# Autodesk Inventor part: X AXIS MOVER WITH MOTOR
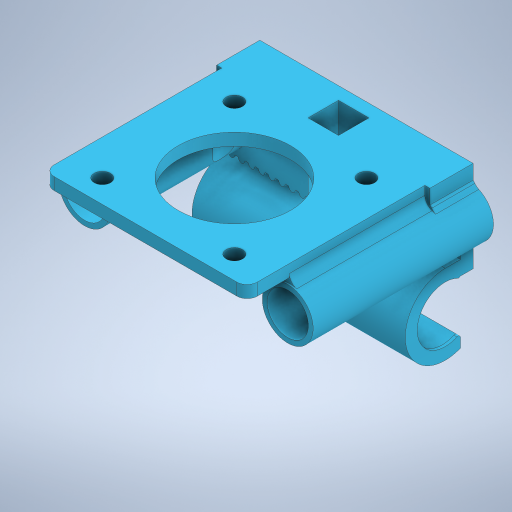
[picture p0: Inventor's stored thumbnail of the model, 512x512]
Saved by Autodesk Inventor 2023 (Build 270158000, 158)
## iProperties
Created: 2025-07
Part Number: X AXIS MOVER WITH MOTOR
Material: Generic
Document SubType Name: Modeling
Designer: erjon
Density: 1 g/cm^3
Appearance: Default
Author: erjon
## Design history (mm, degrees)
feature "Base1"
sketch "Sketch1"
  geometry: L1 (-7, 2)-(-7, -0.943); L2 (-9.308, -3.538)-(-9.241, -3.404) reference; L3 (-5, -5)-(-9, -5) reference; L4 (0, 10.101)-(0, 0) reference; L5 (-9.399, 7.335)-(-9.5, 7.5) reference; L6 (-10, 8)-(-10, 9) reference; L7 (-10, 9)-(0, 9); L8 (-4.692, -3.538)-(-4.759, -3.404); L9 (-9, -5)-(-5, -5); L10 (-14, 10.101)-(-14, 0); L11 (-4.601, 7.335)-(-4.5, 7.5); L12 (-4, 8)-(-4, 9); L13 (-4, 9)-(-14, 9); A1 r 5.85 centre (-7, 2) between (-9.241, -3.404) and (-9.399, 7.335) reference; A2 r 1 centre (-9, -4) between (-10, -4) and (-9, -5) reference; A3 r 0.5 centre (-9.5, -4) between (-9.308, -3.538) and (-10, -4) reference; A4 r 5 centre (-5, 0) between (-5, -5) and (0, 0) reference; A5 r 0.5 centre (-9.5, 8) between (-10, 8) and (-9.5, 7.5) reference; A6 r 0.5 centre (-4.5, -4) between (-4, -4) and (-4.692, -3.538); A7 r 1 centre (-5, -4) between (-5, -5) and (-4, -4); A8 r 5 centre (-9, 0) between (-14, 0) and (-9, -5); A9 r 5.85 centre (-7, 2) between (-4.601, 7.335) and (-4.759, -3.404); A10 r 0.5 centre (-4.5, 8) between (-4.5, 7.5) and (-4, 8); 9 further points
  constraints: 16 end point, 16 symmetric about line, 10 point on circle, 5 centre point, 2 point on line, 1 perpendicular, 1 vertical, 5 other
extrude "Extrusion1" join sketch "Sketch1" stored distance "d0" = 10; taper "d1" = 0 deg
sketch "Sketch2"
  geometry: L1 (-4.601, 7.335)-(0, 7.335); L2 (0, 0)-(0, 10.101) reference; A1 r 5.85 centre (-7, 2) between (-9.241, -3.404) and (-9.399, 7.335) reference; 1 further point
  constraints: 2 end point, 1 horizontal, 1 point on circle, 1 point on line
extrude "Extrusion2" cut sketch "Sketch1" distance "d2" = 100; taper "d3" = 0 deg
sketch "Sketch3"
  geometry: L1 (9.399, 7.335)-(9.5, 7.5) reference; L2 (10, 8)-(10, 9) reference; L3 (4, 9)-(14, 9) reference; L4 (14, 0)-(14, 10.101) reference; L5 (9.399, 7.335)-(14, 7.335) reference; A1 r 0.5 centre (9.5, 8) between (9.5, 7.5) and (10, 8) reference; 1 further point
extrude "Extrusion3" join sketch "Sketch3" stored distance "d4" = 100; taper "d5" = 0 deg
sketch "Sketch4"
  geometry: L1 (42, -15.065)-(42, -12.299) reference; L2 (42, 0)-(42, -1.858) reference; L3 (0, 0)-(42, 0) reference; L4 (0, 0)-(0, -1.858) reference; L5 (0, -12.299)-(0, -15.065) reference; L6 (0, -15.065)-(42, -15.065) reference; A1 r 5 centre (41, -7.4) between (42, -12.299) and (43.122, -2.873) reference; A2 r 2 centre (43.971, -1.062) between (42.348, -2.231) and (43.122, -2.873) reference; A3 r 2 centre (40.726, -3.4) between (42.348, -2.231) and (42, -1.858) reference; A4 r 2 centre (1.274, -3.4) between (0, -1.858) and (-0.348, -2.231) reference; A5 r 2 centre (-1.971, -1.062) between (-1.122, -2.873) and (-0.348, -2.231) reference; A6 r 5 centre (1, -7.4) between (-1.122, -2.873) and (0, -12.299) reference; 1 further point
extrude "Extrusion4" cut sketch "Sketch4" distance "d6" = 1.5; taper "d7" = 0 deg
sketch "Sketch5"
  geometry: L1 (29.255, -6)-(-0.745, -6); L2 (14.255, -6)-(14.255, -11.978); L3 (14.255, -11.978)-(11.256, -12); L4 (35.255, -12)-(-6.745, -12) reference; L5 (11.256, -12)-(17.256, -12); L6 (17.256, -12)-(17.256, 0); L7 (25.305, 0)-(3.205, 0) reference; L8 (17.256, 0)-(11.256, 0); L9 (11.256, 0)-(11.256, -13.665); L10 (-6.745, -13.665)-(35.255, -13.665) reference; A1 r 5 centre (34.255, -6) between (30.465, -2.739) and (35.255, -10.899) reference; A2 r 5 centre (-5.745, -6) between (-6.745, -10.899) and (-1.641, -3.143) reference; 3 further points
  constraints: 14 end point, 4 point on line, 3 perpendicular, 2 point on circle, 1 horizontal, 1 midpoint, 1 vertical
  dimensions: "d8" = 3 distance of L2.end L3.end; "d9" = 6 distance of L3.end L5.end; "d10" = 6 distance of L6.end L8.end
extrude "Extrusion5" cut sketch "Sketch5" distance "d11" = 6; taper "d12" = 0 deg
sketch "Sketch6"
  geometry: L1 (34.087, -35)-(34.087, -8.324) reference; L2 (34.087, -8.324)-(38, -8.324) reference; L3 (38, -2)-(38, -8.324) reference; L4 (0, 0)-(36, 0) reference; L5 (-2, -8)-(-2, -2) reference; L6 (-2, -8)-(3.745, -8) reference; L7 (3.745, -29.508)-(3.745, -8) reference; L8 (3.745, -35)-(3.745, -31.492) reference; L9 (15, -35)-(3.745, -35) reference; L10 (15, -35)-(15, -41) reference; L11 (15, -41)-(21, -41) reference; L12 (21, -35)-(21, -41) reference; L13 (34.087, -35)-(21, -35) reference; L14 (21, -35)-(15, -35); C1 r 1.6 at (31, -4.5) reference; C2 r 1.6 at (5, -4.5) reference; C3 r 1.6 at (31, -30.5) reference; C4 r 11.05 at (18, -17.5) reference; A1 r 2 centre (36, -2) between (38, -2) and (36, 0) reference; A2 r 2 centre (0, -2) between (0, 0) and (-2, -2) reference; A3 r 1.6 centre (5, -30.5) between (3.745, -31.492) and (3.745, -29.508) reference; 1 further point
  constraints: 2 end point, 1 horizontal
extrude "Extrusion6" cut sketch "Sketch6" distance "d13" = 6; taper "d14" = 0 deg
sketch "Sketch7"
  geometry: L1 (-6, 0)-(0, 0) reference; L2 (-6, 0)-(-6, -0.8); L3 (-6, -0.148)-(-6, 0) reference; L4 (-6, -0.8)-(4, -0.8); L5 (4, -0.148)-(4, -9.148) reference; L6 (4, -0.8)-(4, 0); L7 (4, 0)-(-6, 0); 3 further points
  constraints: 8 end point, 2 perpendicular, 1 collinear, 1 point on line, 1 vertical
  dimensions: "d15" = 0.8 distance of L1.start L2.end
extrude "Extrusion7" cut sketch "Sketch7" distance "d16" = 100; taper "d17" = 0 deg
fillet "Fillet1" dims "d18" = 4
sketch "Sketch8"
  geometry: L1 (0, -0.8)-(-6, -0.8) reference; L2 (-6, -0.8)-(-6, 0) reference; L3 (-6, 0)-(0, 0) reference; L4 (0, 0)-(0, 0.953) reference; L5 (0, 0.953)-(-8.5, 0.953) reference; L6 (-8.5, 0.953)-(-8.5, -1.813) reference; L7 (-5.399, -1.813)-(-8.5, -1.813) reference; L8 (-5.241, -12.552)-(-5.308, -12.686) reference; L9 (-5, -14.148)-(-1, -14.148) reference; L10 (4, -4.8)-(4, -9.148) reference; L11 (-6, -0.8)-(-8.5, -0.8); A1 r 4 centre (0, -4.8) between (4, -4.8) and (0, -0.8) reference; A2 r 5.85 centre (-3, -7.148) between (-5.241, -12.552) and (-5.399, -1.813) reference; A3 r 0.5 centre (-5.5, -13.148) between (-5.308, -12.686) and (-6, -13.148) reference; A4 r 1 centre (-5, -13.148) between (-6, -13.148) and (-5, -14.148) reference; A5 r 5 centre (-1, -9.148) between (-1, -14.148) and (4, -9.148) reference; 1 further point
  constraints: 2 end point, 1 perpendicular, 1 point on line
extrude "Extrusion8" cut sketch "Sketch8" distance "d19" = 100; taper "d20" = 0 deg
sketch "Sketch9"
  geometry: L1 (0, 0.005)-(-6, 0.005) reference; L2 (-6, 0.005)-(-6, -0.895); L3 (-6, -0.895)-(-8.5, -0.895); L4 (-6, -0.8)-(-8.5, -0.8) reference; L5 (-8.5, -0.895)-(-8.5, -0.8); L6 (-8.5, -0.895)-(-8.5, -2.895); L7 (-8.5, -2.895)-(0, -2.895); L8 (0, -2.895)-(0, -0.895); L9 (-6, -0.895)-(0, -0.895); L10 (-8.5, -2.895)-(-8.5, -8.745); L11 (-8.5, -8.745)-(-3, -8.745); L12 (-6, -0.895)-(-6, -16); L13 (-8.5, -0.8)-(-6, -0.8) reference; L14 (-6, -0.8)-(-6, 0) reference; L15 (-6, 0)-(0, 0) reference; L16 (0, 0)-(0, 0.953) reference; L17 (0, 0.953)-(-8.5, 0.953) reference; L18 (-8.5, 0.953)-(-8.5, -0.8) reference; L19 (-6, -3.723)-(-8.5, -3.723); 5 further points
  constraints: 22 end point, 8 perpendicular, 3 vertical, 2 coincident, 2 point on line, 1 horizontal, 6 other
  dimensions: "d21" = 0.9 distance of L1.end L2.end; "d22" = 2 distance of L3.end L6.end; "d23" = 5.85 distance of L6.end L10.end; "d24" = 5.5 distance of L10.end L11.end
extrude "Extrusion9" join sketch "Sketch9" stored distance "d25" = 100; taper "d26" = 0 deg
sketch "Sketch10"
  geometry: L1 (-6, -0.895)-(-6, 0) reference; L2 (-6, 0)-(0, 0) reference; L3 (0, 0)-(0, 0.953) reference; L4 (0, 0.953)-(-8.5, 0.953) reference; L5 (-8.5, 0.953)-(-8.5, -3.723) reference; L6 (-8.5, -3.723)-(-6, -3.723) reference; L7 (-6, -13.768)-(-6, -16) reference; L8 (-3, -0.895)-(-6, -0.895) reference; L9 (-6, -13.768)-(-6, -3.723); C1 r 5.85 at (-3, -8.745); C2 r 5.5 at (-3, -8.745); A1 r 5.85 centre (-3, -8.745) between (-6, -13.768) and (-6, -3.723) reference; A2 r 7.85 centre (-3, -8.745) between (-6, -16) and (-3, -0.895) reference; 3 further points
  constraints: 2 centre point, 2 coincident, 2 end point, 1 concentric, 1 vertical
  dimensions: "d27" = 11 diameter of C2
extrude "Extrusion10" join sketch "Sketch10" distance "d28" = 0.6; taper "d29" = 0 deg
fillet "Fillet2" dims "d30" = 0.5
sketch "Sketch11"
  geometry: A1 r 5.5 centre (3, -8.745) between (5.432, -3.812) and (5.292, -13.745) reference; A2 r 0.5 centre (5.5, -14.2) between (5.857, -13.85) and (5.292, -13.745) reference; A3 r 5.85 centre (3, -8.745) between (6, -3.723) and (5.857, -13.85) reference; A4 r 0.5 centre (5.653, -3.364) between (5.432, -3.812) and (6, -3.723) reference; 1 further point
extrude "Extrusion11" join sketch "Sketch11" distance "d31" = 0.6; taper "d32" = 0 deg
sketch "Sketch12"
  geometry: C1 r 4.05 at (0, 0) reference; C2 r 4.1 at (0, 0); C3 r 4.05 at (-40, 0) reference; C4 r 4.1 at (-40, 0); 1 further point
  constraints: 2 centre point, 2 coincident
  dimensions: "d33" = 8.2 diameter of C2; "d34" = 8.2 diameter of C4
extrude "Extrusion12" cut sketch "Sketch12" distance "d35" = 21; taper "d36" = 0 deg
sketch "Sketch13"
  geometry: L1 (15, 41)-(21, 41) reference; L2 (21, 41)-(21, 35) reference; L3 (21, 35)-(15, 35) reference; L4 (15, 35)-(15, 41) reference; L5 (39, 43.5)-(-3, 43.5) reference; L6 (-3, 43.5)-(-3, 35) reference; L7 (-3, 35)-(-2, 35) reference; L8 (-2, 35)-(-2, 2) reference; L9 (0, 0)-(36, 0) reference; L10 (38, 2)-(38, 35) reference; L11 (38, 35)-(39, 35) reference; L12 (39, 35)-(39, 43.5) reference; C1 r 11.05 at (18, 17.5) reference; C2 r 1.6 at (31, 30.5) reference; C3 r 1.6 at (5, 4.5) reference; C4 r 1.6 at (5, 30.5) reference; C5 r 1.6 at (31, 4.5) reference; A1 r 2 centre (0, 2) between (-2, 2) and (0, 0) reference; A2 r 2 centre (36, 2) between (36, 0) and (38, 2) reference; 1 further point
extrude "Extrusion13" join sketch "Sketch13" distance "d37" = 1; taper "d38" = 0 deg
body "Solid1"
node "Projected Loop1"
node "Projected Loop2"
node "Projected Loop3"
node "Projected Loop4"
node "Projected Loop5"
node "Projected Loop6"
